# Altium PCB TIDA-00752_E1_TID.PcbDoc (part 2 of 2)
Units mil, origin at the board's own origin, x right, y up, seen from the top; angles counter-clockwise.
Board outline 600 x 3728.74 mil, 4 copper layers (Top Layer, GND, PWR, Bottom Layer), stack 62.2 mil thick; 88 components, 42 nets, 233 pads, 115 vias.
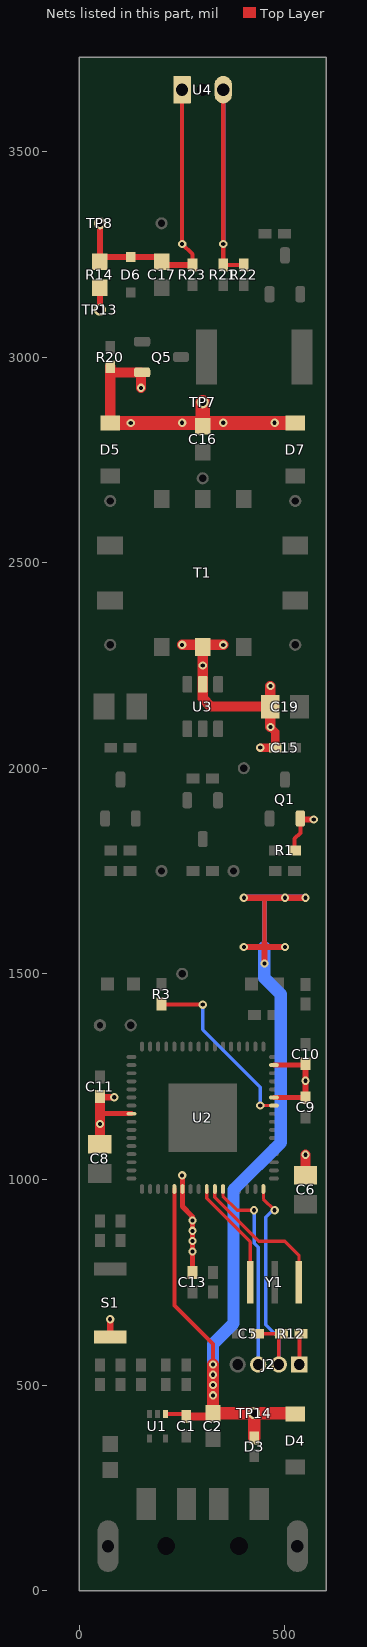
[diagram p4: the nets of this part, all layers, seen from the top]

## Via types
v1: diameter 20, hole 10, Top Layer to Bottom Layer, tented both sides, 102 vias
v2: diameter 19.68, hole 7.87, Top Layer to Bottom Layer, tented both sides, 13 vias

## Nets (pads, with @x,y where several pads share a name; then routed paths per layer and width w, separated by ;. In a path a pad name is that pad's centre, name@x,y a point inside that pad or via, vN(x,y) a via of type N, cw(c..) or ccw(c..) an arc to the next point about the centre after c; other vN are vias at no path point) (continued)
RLED: R3.1 U2.10 | length 437
  Top Layer w8: v1(440,1180) 472.76,1180 U2.10@473.23,1179.53
  Top Layer w10: R3.1@200,1426.38 201.38,1425 v1(300,1425)
  Bottom Layer w8: v1(300,1425) 300,1364.38 440,1224.38 v1(440,1180)
SBWTCK: J2.3 U2.59 | length 486.5
  Top Layer w8: U2.59@349.22,976.78 349.22,959.54 383.76,925 v1(425,925)
  Bottom Layer w8: v1(425,925) 425,845 435,835 J2.3@435,550
SBWTDIO: C5.1 J2.2 R12.2 U2.64 | length 603.1
  Top Layer w8: C5.1@433.62,625 R12.2@491.38,625 485,618.62 J2.2@485,550 ; U2.64@447.67,976.78 447.67,952.33 v1(475,925) v1@470.34,925
  Bottom Layer w8: v1(475,925) 470.34,925 453.13,907.78 453.13,646.87 485,615 J2.2@485,550
VBUS: C1.1 C2.1 C15.1 C19.1 D3.1 D4.1 Q1.2 R1.1 T1.2 TP14.1 U1.1 U2.53 U3.2 | length 4273.8
  Top Layer w10: U1.1@209.69,429.53 C1.1@254.09,429.53 ; U2.53@231.08,976.78 231.08,693.92 325,600 v1(325,550) ; 450,1565 450,1685 ; R1.1@523.62,1800 523.62,1828.62 537.4,1842.4 Q1.2@537.4,1877.76 Q1.2@540.16,1875
  Top Layer w15: v1(400,1565) 450,1565 v1(500,1565) ; v1(400,1685) 450,1685 v1(500,1685) v1(550,1685) ; v1(450,1525) 450,1575 ; Q1.2@540.16,1875 v1(570,1875)
  Top Layer w20: C1.1@260,423.62 C2.1@317.13,423.62 ; v1(440,2050) C15.1@476.38,2050 476.38,2088.18 v1(464.57,2099.99)
  Top Layer w25: v1(250,2300) T1.2@295,2300 ; T1.2@300,2295 U3.2@300,2204.13 300,2170 320.01,2149.99 C19.1@464.57,2149.99 ; T1.2@305,2300 v1(350,2300) ; v1(464.57,2099.99) C19.1@464.57,2149.99 ; v1(464.57,2200) C19.1@464.57,2149.99
  Top Layer w30: v1(325,550) C2.1@325,431.5 TP14.1@425,431.5 ; D3.1@425,371.65 TP14.1@425,431.5 ; D4.1@522.03,431.5 TP14.1@425,431.5
  GND w10: v1(400,1565) 450,1565 ; v1(400,1685) 450,1685 ; v1(450,1525) 450,1565 ; v1(500,1565) 450,1565 ; v1(550,1685) 450,1685 ; 450,1565 450,1685
  PWR w10: v1(450,1525) 450,1685
  PWR w15: v1(400,1565) v1(500,1565)
  Bottom Layer w10: 450,1565 450,1685
  Bottom Layer w15: v1(400,1565) 450,1565 v1(500,1565) ; v1(400,1685) 450,1685 v1(550,1685)
  Bottom Layer w30: v1(325,475) 325,600 375,650 375,975 490,1090 490,1450 450,1490 450,1565
  other v1: 325,500 325,525 300,2250
VCC: C16.1 D5.1 D7.1 Q5.2 R14.1 R20.2 TP7.1 TP13.1 | length 800.4
  Top Layer w15: TP13.1@50,3115 R14.1@50,3160
  Top Layer w25: D5.1@75,2839.46 R20.2@75,2976.37 ; R20.2@77.6,2962.59 150,2962.59 v1(150,2925)
  Top Layer w35: D5.1@75,2839.46 C16.1@300,2839.46 ; C16.1@300,2831.49 C16.1@300,2839.46 ; TP7.1@300,2890 C16.1@300,2839.46 ; D7.1@525,2839.46 C16.1@300,2839.46
  other v1: 125,2839.46 250,2840 350,2840 475,2840
VN: R21.1 R22.2 U4.2 | length 851.4
  Top Layer w10: U4.2@350,3650 R21.1@350,3223.62 R22.2@400,3223.62
  Bottom Layer w10: v1(350,3275) U4.2@350,3650
VP: C17.1 D6.1 R14.2 R23.2 TP8.1 U4.1 | length 1134.8
  Top Layer w10: U4.1@250,3650 v1(250,3275) 275,3250 R23.2@275,3223.62
  Top Layer w15: R14.2@50,3231.5 61.81,3243.31 D6.1@125,3243.31 188.19,3243.31 C17.1@200,3231.5 207.87,3223.62 R23.2@275,3223.62 ; R14.2@50,3240 TP8.1@50,3325
  Bottom Layer w10: v1(250,3275) U4.1@250,3650
VUSB: C6.1 C8.1 C9.1 C10.1 C11.1 C13.1 J2.1 R12.1 S1.2 U2.11 U2.15 U2.40 U2.54 | length 879.9
  Top Layer w10: J2.1@535,550 R12.1@535,621.38 ; C9.1@549.41,1199.22 C9.1@550,1198.62
  Top Layer w12: 50,1160 U2.40@126.77,1160 ; C11.1@50,1201.38 55,1196.37 C11.1@58.63,1200 ; v1(250,1010) 250.77,1009.23 U2.54@250.77,976.78 250.77,934.23 275,910 C13.1@275,773.62 ; U2.11@473.23,1199.22 C9.1@549.41,1199.22 ; U2.15@473.23,1277.96 C10.1@546.58,1277.96 ; R12.1@535,621.38 R12.1@538.62,625
  Top Layer w15: C11.1@58.63,1200 v1(85,1200) ; S1.2@75,617.32 v1(75,660) ; C9.1@550,1198.62 C10.1@550,1281.38
  Top Layer w25: C8.1@50,1085.44 v1(50,1135) C11.1@50,1201.38 ; C6.1@550,1010.43 v1(550,1060)
  other v1: 275,825 275,850 275,875 275,900 550,1240
XT2IN: U2.57 Y1.3 | length 270.7
  Top Layer w8: U2.57@309.84,976.78 309.84,954.02 415.94,847.92 Y1.3@415.94,750
XT2OUT: U2.58 Y1.1 | length 348.8
  Top Layer w8: U2.58@329.53,976.78 329.53,956.78 436.31,850 500,850 534.06,815.94 Y1.1@534.06,750
pads on no net: J1.7 J1.8 U2.1 U2.2 U2.3 U2.4 U2.5 U2.6 U2.7 U2.12 U2.13 U2.19 U2.21 U2.22 U2.23 U2.25 U2.26 U2.27 U2.29 U2.31 U2.32 U2.33 U2.34 U2.35 U2.36 U2.37 U2.38 U2.41 U2.43 U2.44 U2.45 U2.46 U2.47 U2.48 U2.60 U2.61 U2.62 U2.63 U3.6 U4.MH

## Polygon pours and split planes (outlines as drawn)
GND on Top Layer "Component Side-No Net 3" (solid, remove dead copper, pour order 42): 190,145 185,140 140,140 135,145 135,310 140,315 185,315 190,310 190,145
ISOGND on GND "Signal Layer 1-No Net" (solid, remove dead copper, pour order 9): 0,2625 600,2625 600,3350 0,3350 0,2625
GND on GND "Signal Layer 1-No Net 1" (solid, remove dead copper, pour order 11): 0,2325 0,1650 600,1650 600,2325 0,2325
GND on GND "Signal Layer 1-No Net 2" (solid, remove dead copper, pour order 34): 600,0 0,0 0,1600 600,1600 600,0
VCC on PWR "Component Side-No Net 1" (solid, remove dead copper, pour order 17): 600,2800 0,2800 0,3200 120,3200 125,3195 125,3080 130,3075 600,3075 600,2800
VUSB on PWR "Signal Layer 2-No Net" (solid, remove dead copper, pour order 32): 600,500 0,500 0,1500 600,1500 600,500
VBUS on PWR "Signal Layer 2-No Net 1" (solid, remove dead copper, pour order 36): 600,1650 0,1650 0,2325 600,2325 600,1650
GND on Bottom Layer "Solder Side-No Net" (solid, remove dead copper, pour order 52): 0,0 0,1600 600,1600 600,0 0,0
GND on Bottom Layer "Solder Side-No Net 1" (solid, remove dead copper, pour order 54): 600,1650 0,1650 0,2325 600,2325 600,1650
ISOGND on Bottom Layer "Solder Side-No Net 2" (solid, remove dead copper, pour order 56): 0,2625 0,3350 600,3350 600,2625 0,2625

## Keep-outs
Keep-Out Layer:
  lines w5: 600,0 600,0
  lines w10: -5,-5 -5,3733.74 605,3733.74 605,-5 -5,-5
  text ".Layer_Name" at 577,-1758.49 h60

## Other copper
Top Layer:
  rectangle net EN_PWR: 135,1540 165,1590
  rectangle net DATA_OUT: 235,1540 265,1590
  rectangle net DATA_OUT_NOT: 335,1540 365,1590
  rectangle net VBUS: 435,1540 465,1590
  rectangle net EN_PWR: 135,1660 165,1710
  rectangle net DATA_OUT: 235,1660 265,1710
  rectangle net DATA_OUT_NOT: 335,1660 365,1710
  rectangle net VBUS: 435,1660 465,1710
  rectangle net VP: 235,3410 265,3460
  rectangle net VN: 335,3410 365,3460
  rectangle net VP: 235,3290 265,3340
  rectangle net VN: 335,3290 365,3340
  text ".Layer_Name" at 577,-1758.49 h60
GND:
  text "GND" at 704,-1754 h40
PWR:
  text "PWR" at 694,-1760 h40
Bottom Layer:
  rectangle net GND: 135,1540 165,1590
  rectangle net GND: 235,1540 265,1590
  rectangle net GND: 335,1540 365,1590
  rectangle net VBUS: 435,1540 465,1590
  rectangle net GND: 135,1660 165,1710
  rectangle net GND: 235,1660 265,1710
  rectangle net GND: 335,1660 365,1710
  rectangle net VBUS: 435,1660 465,1710
  rectangle net VP: 235,3410 265,3460
  rectangle net VN: 335,3410 365,3460
  rectangle net VP: 235,3290 265,3340
  rectangle net VN: 335,3290 365,3340
  text ".Layer_Name" at 577,-1758.49 h60

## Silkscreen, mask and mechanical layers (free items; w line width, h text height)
Top Overlay:
  circle w6: c500,1000 r5
  circle w6: c200,2255 r5
  circle w6: c437,275 r5
  circle w6: c337,2240 r5
  circle w6: c250,3580 r5
  circle w6: c210,455 r5
  lines w6: 62.79,13 62.79,42 ; 102,147.64 496,147.64 ; 537.2,11.2 537.2,42
  lines w10: 5,5 5,2330 595,2330 595,5 5,5 ; 5,2620 595,2620 595,3724 5,3724 5,2620
  text "LMT01" at 35,3650 h50
  text ".Layer_Name" at 577,-1758.49 h60
Bottom Overlay:
  lines w10: 5,5 595,5 595,2330 5,2330 5,5 ; 5,2620 595,2620 595,3724 5,3724 5,2620
  text "Barrier" at 35,2600 h40 r180
  text "Isolation" at 575,2575 h40
  text "Isolation" at 25,2375 h40 r180
  text "Barrier" at 565,2350 h40
  text ".PCB_Rev" at 500,1225 h60 r270
  text ".PRJ_Number" at 500,625 h60 r270
  text ".Layer_Name" at 577,-1758.49 h60
Top Paste:
  text ".Layer_Name" at 577,-1758.49 h60
Bottom Paste:
  text ".Layer_Name" at 577,-1758.49 h60
Top Solder:
  region: 140,1590 135,1585 135,1545 140,1540 160,1540 165,1545 165,1585 160,1590
  region: 240,1590 235,1585 235,1545 240,1540 260,1540 265,1545 265,1585 260,1590
  region: 340,1590 335,1585 335,1545 340,1540 360,1540 365,1545 365,1585 360,1590
  region: 440,1590 435,1585 435,1545 440,1540 460,1540 465,1545 465,1585 460,1590
  region: 140,1710 135,1705 135,1665 140,1660 160,1660 165,1665 165,1705 160,1710
  region: 240,1710 235,1705 235,1665 240,1660 260,1660 265,1665 265,1705 260,1710
  region: 340,1710 335,1705 335,1665 340,1660 360,1660 365,1665 365,1705 360,1710
  region: 440,1710 435,1705 435,1665 440,1660 460,1660 465,1665 465,1705 460,1710
  region: 340,3460 335,3455 335,3415 340,3410 360,3410 365,3415 365,3455 360,3460
  region: 240,3460 235,3455 235,3415 240,3410 260,3410 265,3415 265,3455 260,3460
  region: 340,3340 335,3335 335,3295 340,3290 360,3290 365,3295 365,3335 360,3340
  region: 240,3340 235,3335 235,3295 240,3290 260,3290 265,3295 265,3335 260,3340
  text ".Layer_Name" at 577,-1758.49 h60
  text ".Layer_Name" at 577,-1758.49 h60
Bottom Solder:
  region: 140,1590 135,1585 135,1545 140,1540 160,1540 165,1545 165,1585 160,1590
  region: 240,1590 235,1585 235,1545 240,1540 260,1540 265,1545 265,1585 260,1590
  region: 340,1590 335,1585 335,1545 340,1540 360,1540 365,1545 365,1585 360,1590
  region: 440,1590 435,1585 435,1545 440,1540 460,1540 465,1545 465,1585 460,1590
  region: 140,1710 135,1705 135,1665 140,1660 160,1660 165,1665 165,1705 160,1710
  region: 240,1710 235,1705 235,1665 240,1660 260,1660 265,1665 265,1705 260,1710
  region: 340,1710 335,1705 335,1665 340,1660 360,1660 365,1665 365,1705 360,1710
  region: 440,1710 435,1705 435,1665 440,1660 460,1660 465,1665 465,1705 460,1710
  region: 240,3460 235,3455 235,3415 240,3410 260,3410 265,3415 265,3455 260,3460
  region: 340,3460 335,3455 335,3415 340,3410 360,3410 365,3415 365,3455 360,3460
  region: 240,3340 235,3335 235,3295 240,3290 260,3290 265,3295 265,3335 260,3340
  region: 340,3340 335,3335 335,3295 340,3290 360,3290 365,3295 365,3335 360,3340
  text ".Layer_Name" at 577,-1758.49 h60
Drill Guide:
  text ".Layer_Name" at 577,-1758.49 h60
Mechanical 1:
  lines w5: 0,1600 cw(c0,1625) 0,1650 110,1650 cw(c110,1625) 110,1600 0,1600 ; 0,3350 cw(c0,3375) 0,3400 210,3400 cw(c210,3375) 210,3350 0,3350 ; 190,1600 cw(c190,1625) 190,1650 210,1650 cw(c210,1625) 210,1600 190,1600 ; 290,1600 cw(c290,1625) 290,1650 310,1650 cw(c310,1625) 310,1600 290,1600 ; 290,3350 cw(c290,3375) 290,3400 310,3400 cw(c310,3375) 310,3350 290,3350 ; 390,1600 cw(c390,1625) 390,1650 410,1650 cw(c410,1625) 410,1600 390,1600 ; 390,3350 cw(c390,3375) 390,3400 600,3400 cw(c600,3375) 600,3350 390,3350 ; 490,1600 cw(c490,1625) 490,1650 600,1650 cw(c600,1625) 600,1600 490,1600
  lines w10: 0,0 0,3728.74 600,3728.74 600,0 0,0
Mechanical 2:
  rectangle: 0,-1175 125,-1050
  rectangle: 125,-1300 500,-1175
  lines w7: 0,-1175 1000,-1175 ; 125,-1300 125,-1050 ; 250,-1300 250,-1050 ; 500,-1300 500,-1050 ; 750,-1300 750,-1050 ; 0,-1300 1000,-1300 1000,-1050 0,-1050 0,-1300
Mechanical 3:
  text ".Layer_Name" at 577,-1758.49 h60
Mechanical 4:
  text ".Layer_Name" at 577,-1758.49 h60
Mechanical 5:
  circle w6: c250,3645 r5
  circle w6: c462,3137 r6.4
  circle w6: c136,3038 r7.62
  circle w6: c62,1862 r5.39
  circle w6: c336,1934 r4.47
  circle w6: c462,1867 r5.39
  circle w6: c494,1001 r4.47
  circle w6: c209,444 r3.16
  circle w6: c536,551 r9.49
  circle w6: c436,253 r6.26
  lines w10: -292,-1830.17 6308,-1830.17 ; -292,-1626.83 6310,-1626.83 ; -292,-1423.5 -292,-2033.5 3713,-2033.5 6310,-2033.5 6310,-1423.5 -291.5,-1423.5 -291.5,-2033.5 1284,-2033.5 ; 2173,-2033.5 2173,-1423.5 ; 3440,-1626.83 3440,-1423.5 ; 4280,-1626.83 4280,-1423.5 ; 4902,-2040 4902,-1837.17
  text "COMPONENTS MARKED 'DNP' SHOULD NOT BE POPULATED." at 1153.5,-1218.5 h25
  text "ASSEMBLY VARIANT:" at 1153,-1334 h25
  text ".VariantName" at 2189,-1334 h25
  text "PCB VIEWED FROM TOP SIDE" at -228.5,-1555.67 h25
  text "BOARD #:" at 2248,-1555.67 h25
  text ".PRJ_Number" at 2793.5,-1555.67 h25
  text "REV:" at 3638,-1555.67 h25
  text ".PCB_Rev" at 3929.5,-1555.67 h25
  text "SVN REV:" at 4476,-1555.67 h25
  text ".VersionControl_RevNumber" at 4982,-1555.67 h25
  text "LAYER NAME = Assembly Top" at -70,-1749 h30
  text "TID #:" at 2248,-1759 h25
  text ".TID" at 2793.5,-1759 h25
  text "PLOT NAME =" at -228.5,-1964.34 h25
  text ".plot_File_Name" at 577,-1964.34 h25
  text "GENERATED    :" at 2250,-1964.34 h25
  text ".Print_Date" at 3119.5,-1964.34 h25
  text ".Print_Time" at 3848.5,-1964.34 h25
  text "TEXAS INSTRUMENTS" at 5113,-1964.34 h25
Mechanical 6:
  lines w10: -292.5,-1627.33 6309.5,-1627.33 ; -290.5,-1830.67 6309.5,-1830.67 ; 1115.5,-2040.5 1115.5,-1837.67 ; 1737.5,-1627.33 1737.5,-1424 ; 2577.5,-1627.33 2577.5,-1424 ; 3844.5,-2034 3844.5,-1424 ; 4733.5,-2034 6309,-2034 6309,-1424 -292.5,-1424 -292.5,-2034 2304.5,-2034 6309.5,-2034 6309.5,-1424
  text "COMPONENTS MARKED 'DNP' SHOULD NOT BE POPULATED." at 6102,-1218 h60
  text ".VariantName" at 5058,-1334 h60
  text "ASSEMBLY VARIANT:" at 6097,-1334 h60
  text ".VersionControl_RevNumber" at 1035.5,-1556.17 h60
  text "SVN REV:" at 1541.5,-1556.17 h60
  text ".PCB_Rev" at 2088,-1556.17 h60
  text "REV:" at 2379.5,-1556.17 h60
  text ".PRJ_Number" at 3224,-1556.17 h60
  text "BOARD #:" at 3769.5,-1556.17 h60
  text "PCB VIEWED FROM BOTTOM SIDE" at 6246,-1556.17 h60
  text ".TID" at 3224,-1759.5 h60
  text "TID #:" at 3769.5,-1759.5 h60
  text "TEXAS INSTRUMENTS" at 904.5,-1964.84 h60
  text ".Print_Time" at 2169,-1964.84 h60
  text ".Print_Date" at 2898,-1964.84 h60
  text "GENERATED    :" at 3767.5,-1964.84 h60
  text ".plot_File_Name" at 5440.5,-1964.84 h60
  text "PLOT NAME =" at 6246,-1964.84 h60
Mechanical 9:
  drawing of 59 lines, arcs and shapes, not listed
  text "1" at 739.84,7136.5 h70
  text "2" at 3235.5,7136.5 h70
  text "3" at 5724.84,7136.5 h70
  text "4" at 8231.51,7136.5 h70
  text "5" at 10730.5,7136.5 h70
  text "6" at 13235.5,7136.5 h70
  text "A" at -416.5,5993.5 h70
  text "A" at 14383.5,5993.5 h70
  text "B" at -416.5,3613.5 h70
  text "B" at 14383.5,3613.5 h70
  text "C" at -416.5,1238.5 h70
  text "C" at 14383.5,1238.5 h70
  text "PROJECT TITLE:" at 11343.5,-622.5 h45
  text ".PRJ_Title" at 11393.5,-755.83 h70
  text "DESIGNED FOR:" at 11343.5,-923.5 h45
  text ".PRJ_Customer" at 11393.5,-1063.5 h70
  text "D" at -416.5,-1131.5 h70
  text "D" at 14383.5,-1131.5 h70
  text "FILE NAME:" at 11343.5,-1223.5 h45
  text ".PCB_File_Name_No_Path" at 11393.5,-1343.5 h70
  text "Texas Instruments (TI) and/or its licensors do not warrant the accuracy or completeness of this specification" at 6374,-1505.34 h45
  text "ENGINEER:" at 11343.5,-1513.5 h45
  text "LAYOUT BY:" at 12848.5,-1513.5 h45
  text "or any information contained therein. TI and/or its licensors do not warrant that this design will meet" at 6329.01,-1618 h45
  text ".PRJ_Engineer" at 11393.5,-1668.49 h70
  text ".PCB_Layout" at 12899,-1668.49 h70
  text "the specifications, will be suitable for your application or fit for any particular purpose, or will operate in" at 6329.01,-1730.67 h45
  text "ALTIUM DESIGNER VERSION:" at 12848.5,-1823.5 h45
  text "an implementation. TI and/or its licensors do not warrant that the design is production worthy. You should" at 6329.01,-1843.33 h45
  text "completely validate and test your design implementation to confirm the system functionality for your application." at 6374,-1956 h45
  text ".print_Scale" at 11393.5,-1956.83 h70
  text ".Application_BuildNumber" at 12899,-1956.83 h70
  text "1" at 739.84,-2163.5 h70
  text "2" at 3235.5,-2163.5 h70
  text "3" at 5724.84,-2163.5 h70
  text "4" at 8231.51,-2163.5 h70
  text "5" at 10730.5,-2163.5 h70
  text "6" at 13235.5,-2163.5 h70
Mechanical 10:
  drawing of 228 lines, arcs and shapes, not listed
  text "DESIGN INFORMATION" at 12382.02,5910 h60
  text "(REFER ALSO ARRAY/PANEL PROFILING INFORMATION)" at 12020.46,5748.29 h60
  text "BOARD SIZE" at 11334.46,5744 h60
  text "600MIL" at 11796.78,5616.18 h60
  text "X" at 12302.46,5616.18 h60
  text "3728.74MIL" at 12533.78,5616.18 h60
  text "Number of Layers :" at 11737.46,5419 h60
  text "4" at 12832.27,5409 h60
  text "MIN. TRACK WIDTH:" at 11737.46,5280 h60
  text "8" at 12833.7,5280 h60
  text "MIL" at 12988.46,5280 h60
  text "7.874" at 12700,5150 h60
  text "MIN. CLEARANCE:" at 11737.46,5148 h60
  text "MIL" at 12988.46,5148 h60
  text "MIN. VIA DRILL SIZE:" at 11737.46,5016 h60
  text "MIL" at 12988.46,5016 h60
  text "7.874" at 12701,5010 h60
  text "3.785 MIL" at 12432.46,4874.29 h60
  text "MINIMUM ANNULAR RING" at 11408.23,4870 h60
  text "EXTERNAL" at 13140.46,4870 h60
  text "PER" at 11608.23,4752 h60
  text "IPC-D-275 CLASS 2 LEVEL C" at 11828.23,4752 h60
  text "MIL, HOLES" at 13316.46,4639.71 h60
  text "+/-" at 12924,4639 h60
  text "+/-" at 13778,4639 h60
  text "REGISTRATION TOLERANCES:" at 11408.23,4634 h60
  text "METAL" at 12608,4634 h60
  text "5" at 13184.2,4634 h60
  text "3" at 14017.2,4634 h60
  text "MIL" at 14133.46,4634 h60
  text "MATERIAL:" at 11333.46,4424.54 h60
  text "FR-4 High Tg" at 12319.9,4284.21 h60
  text "FR-408" at 11754.46,4275.64 h60
  text "OTHER" at 13242.46,4275.64 h60
  text "X" at 12165,4275 h60
  text "63 MIL (1.6mm) +/-10%" at 12074.56,4112.92 h60
  text "THICKNESS:" at 11408.23,4108.64 h60
  text "X" at 11946.4,4108.64 h60
  text "OTHER" at 13359.46,4108.64 h60
  text "TOLERANCE:" at 11408.23,3950.64 h60
  text "X" at 12247.53,3950.64 h60
  text "ANSI IPC-6012 TYPE 3 CLASS 2" at 12434.48,3950.64 h60
  text "OTHER +/-" at 12434.46,3794.64 h60
  text "BOW & TWIST:" at 11408.23,3637.64 h60
  text "X" at 12247.53,3637.64 h60
  text "ANSI IPC-6012 TYPE 3 CLASS 2" at 12434.48,3637.64 h60
  text "OTHER +/-" at 12434.46,3479.13 h60
  text "COPPER THICKNESS (FINISHED):" at 11333.46,3343.64 h60
  text "1.4MIL (1oz)" at 12213.46,3190.92 h60
  text "2MIL (1.4oz)" at 12980.46,3190.92 h60
  text "2.8MIL (2oz)" at 13707.46,3190.92 h60
  text "OUTER:" at 11690.46,3186.64 h60
  text "X" at 12085,3186 h60
  text "1.4MIL (1oz)" at 12213.46,3033.92 h60
  text "2.8MIL (2oz)" at 12980.46,3033.92 h60
  text "N/A" at 13707,3034.29 h60
  text "INNER SIGNAL:" at 11401.38,3029.64 h60
  text "X" at 12080,3027 h60
  text "DRILLING:" at 11333.46,2890.64 h60
  text "REFERENCE:" at 11408.23,2773.64 h60
  text "X" at 12056.46,2773.64 h60
  text "AS SHOWN" at 12243.46,2773.64 h60
  text "X" at 12957.46,2773.64 h60
  text "NC_DRILL FILES" at 13094.46,2773.64 h60
  text "PTH MIN COPPER THICKNESS:" at 11408.23,2615.64 h60
  text "X" at 12758.46,2615.64 h60
  text "1MIL" at 12895.46,2615.64 h60
  text "OTHER" at 13392.46,2615.64 h60
  text "BOARD FINISH:" at 11333.46,2456.64 h60
  text "SILKSCREEN:" at 11488.68,2338.64 h60
  text "X" at 12437.46,2338.64 h60
  text "TOP" at 12563.46,2338.64 h60
  text "X" at 12947.46,2338.64 h60
  text "BOTTOM" at 13074.46,2338.64 h60
  text "SILKSCREEN COLOR:" at 11488.68,2171.64 h60
  text "X" at 12436.42,2171.64 h60
  text "WHITE" at 12563.46,2171.64 h60
  text "OTHER" at 13074.46,2171.64 h60
  text "SOLDER RESIST COLOR:" at 11488.68,2001.64 h60
  text "X" at 12056.42,1842.44 h60
  text "GREEN" at 12183.46,1842.44 h60
  text "BLUE" at 12774.46,1842.44 h60
  text "OTHER" at 13312.46,1842.44 h60
  text "IMMERSION GOLD (ENIG)" at 12394.46,1653.92 h60
  text "ENEPIG" at 13732,1650.64 h60
  text "SURFACE FINISH:" at 11333.46,1649.64 h60
  text "X" at 12207.51,1649.64 h60
  text "IMM. TIN/SILVER OR EQUIV" at 11663,1492.64 h60
  text "OTHER" at 13094.46,1492.64 h60
  text "ARRAY/PANEL:" at 11333.46,1313.64 h60
  text "CUT AND TRIM PER MECH LAYER 1" at 12394.46,1309.35 h60
  text "N.C. ROUTE" at 12394.46,1157.64 h60
  text "X" at 13073.46,1157.64 h60
  text "V. SCORE" at 13260.46,1157.64 h60
  text "CERTIFICATION:" at 11333.46,1020.64 h60
  text "MATERIALS AND WORKMANSHIP FOR ALL PCBS" at 12058.46,1020.64 h60
  text "TO MEET OR EXCEED THE REQUIREMENTS OF:" at 12058.46,922.64 h60
  text "X" at 11684.96,786.13 h60
  text "ANSI IPC-A-600F CLASS ->" at 11823.96,786.13 h60
  text "X" at 13463.02,786.13 h60
  text "2" at 13581.96,786.14 h60
  text "1" at 13266.96,784.64 h60
  text "3" at 13935.96,784.64 h60
  text "X" at 11687.02,626.64 h60
  text "UL 94V-0" at 11823.96,626.64 h60
  text "X" at 12499.02,626.64 h60
  text "RoHS" at 12635.96,626.64 h60
  text "OTHER" at 13280.36,626.64 h60
  text "PER ORDER" at 13677.42,626.64 h60
  text "X" at 13314,497 h60
  text "VIA TENTING:" at 12551,493 h60
  text "ADDITIONAL REQUIREMENTS:" at 11333.46,485.64 h60
  text "YES" at 13100.67,483.92 h60
  text "NO" at 13465.47,478.69 h60
  text "MICROSECTION:" at 11408.23,370.64 h60
  text "YES" at 12313.96,370.64 h60
  text "IMPEDANCE CONTROL:" at 12573,364 h60
  text "YES" at 13557,363 h60
  text "X" at 14099,356 h60
  text "NO" at 13932.47,345.69 h60
  text "REQUIRED" at 13175.46,214.49 h60
  text "BARE BOARD ELEC. TEST:" at 11408.23,211.64 h60
  text "NONE" at 12713.96,211.64 h60
  text "X" at 13048.46,211.64 h60
  text "PER ORDER" at 13767.46,211.64 h60
  text "MANUFACTURER'S UL:" at 11408.23,54.64 h60
  text "RAIL" at 12573.96,50.35 h60
  text "METAL" at 13065.77,50.35 h60
  text "X" at 13441,50 h60
  text "SILK" at 13577.46,50.35 h60
Mechanical 11:
  lines w10: -292,-1830.17 6308,-1830.17 ; -292,-1626.83 6310,-1626.83 ; -292,-1423.5 -292,-2033.5 3713,-2033.5 6310,-2033.5 6310,-1423.5 -291.5,-1423.5 -291.5,-2033.5 1284,-2033.5 ; 2173,-2033.5 2173,-1423.5 ; 3440,-1626.83 3440,-1423.5 ; 4280,-1626.83 4280,-1423.5 ; 4902,-2040 4902,-1837.17
  text "ALL ARTWORK VIEWED FROM TOP SIDE" at -228.5,-1555.67 h60
  text "BOARD #:" at 2248,-1555.67 h60
  text ".PRJ_Number" at 2793.5,-1555.67 h60
  text "REV:" at 3638,-1555.67 h60
  text ".PCB_Rev" at 3929.5,-1555.67 h60
  text "SVN REV:" at 4476,-1555.67 h60
  text ".VersionControl_RevNumber" at 4982,-1555.67 h60
  text "LAYER NAME =" at -228.5,-1758.49 h60
  text "TID #:" at 2248,-1759 h60
  text ".TID" at 2793.5,-1759 h60
  text "PLOT NAME =" at -228.5,-1964.34 h60
  text ".plot_File_Name" at 577,-1964.34 h60
  text "GENERATED    :" at 2250,-1964.34 h60
  text ".Print_Date" at 3119.5,-1964.34 h60
  text ".Print_Time" at 3848.5,-1964.34 h60
  text "TEXAS INSTRUMENTS" at 5113,-1964.34 h60
Mechanical 12:
  lines w6: 11361,6560 13911,6560 ; 11361,6664.4 13911,6664.4 ; 11301,6075 ccw(c11335,6075) 11335,6041 13937,6041 ccw(c13937,6075) 13971,6075 13971,6781 ccw(c13937,6781) 13937,6815 11335,6815 ccw(c11335,6781) 11301,6781 11301,6075
  text "Layer Stack Up Detail for: TIDA-00752_E1" at 11361,6697.1 h57
  text "Layer" at 11361,6625.4 h24
  text "Gerber" at 12256.81,6625.4 h24
  text "Copper" at 12820.33,6625.4 h24
  text "Dielectric" at 13423.04,6625.4 h24
  text "Name" at 11361,6577.4 h24
  text "Document" at 12256.81,6577.4 h24
  text "Thickness" at 12820.33,6577.4 h24
  text "Material" at 13423.04,6577.4 h24
  text "Top Solder Mask" at 11361,6484.44 h34
  text "(.GTS)" at 12256.81,6484.44 h34
  text "Solder Resist" at 13423.04,6484.44 h34
  text "Top Layer" at 11361,6387.69 h34
  text "(.GTL)" at 12256.81,6387.69 h34
  text "1.4mil" at 12820.33,6387.69 h34
  text "FR-4 High Tg" at 13452,6387 h34
  text "FR-4 High Tg" at 13451,6322 h34
  text "(.G1)" at 12260.81,6320.69 h34
  text "1.4mil" at 12821.33,6316.69 h34
  text "GND" at 11365,6314 h34
  text "FR-4 High Tg" at 13452,6257 h34
  text "1.4mil" at 12824.33,6250.69 h34
  text "(.G2)" at 12260.81,6247.69 h34
  text "PWR" at 11366,6238 h34
  text "FR-4 High Tg" at 13454,6168 h34
  text "Bottom Layer" at 11367,6158 h34
  text "(.GBL)" at 12265,6157 h34
  text "1.4mil" at 12825,6151 h34
  text "Solder Resist" at 13417,6084 h34
  text "(.GBS)" at 12262,6077 h34
  text "Bottom Solder Mask" at 11364,6072 h34
Mechanical 13:
  text ".Layer_Name" at 577,-1758.49 h60
Mechanical 14:
  text ".Layer_Name" at 577,-1758.49 h60
Mechanical 15:
  text ".Layer_Name" at 577,-1758.49 h60
Mechanical 16:
  text ".Layer_Name" at 577,-1758.49 h60
Drill Drawing:
  circle w1: c2482.72,3557.4 r24.89
  circle w1: c2482.72,2661.48 r14.93
  circle w1: c2482.72,2661.48 r24.89
  lines w1: 2457.83,2785.92 2482.72,2798.36 2507.6,2785.92 2495.16,2810.8 2507.6,2835.69 2482.72,2823.25 2457.83,2835.69 2470.27,2810.8 2457.83,2785.92 ; 2457.83,2985.01 2507.6,2985.01 2482.72,2935.24 2457.83,2985.01 ; 2457.83,3097 2470.27,3097 2470.27,3084.56 2495.16,3084.56 2495.16,3097 2507.6,3097 2507.6,3121.89 2495.16,3121.89 2495.16,3134.33 2470.27,3134.33 2470.27,3121.89 2457.83,3121.89 2457.83,3097 ; 2457.83,3258.76 2482.72,3233.88 2507.6,3258.76 2482.72,3283.65 2457.83,3258.76 ; 2457.83,3383.2 2507.6,3383.2 2507.6,3432.97 2457.83,3432.97 2457.83,3383.2 ; 2457.83,3681.84 2457.83,3694.28 2470.27,3706.72 2457.83,3719.17 2457.83,3731.61 2470.27,3731.61 2482.72,3719.17 2495.16,3731.61 2507.6,3731.61 2507.6,3719.17 2495.16,3706.72 2507.6,3694.28 2507.6,3681.84 2495.16,3681.84 2482.72,3694.28 2470.27,3681.84 2457.83,3681.84 ; 2457.83,3843.6 2470.27,3843.6 2482.72,3831.16 2495.16,3843.6 2507.6,3843.6 2495.16,3856.04 2507.6,3868.49 2495.16,3868.49 2482.72,3880.93 2470.27,3868.49 2457.83,3868.49 2470.27,3856.04 2457.83,3843.6
  lines w12: 2390,2591.8 4508.02,2591.8 ; 2390,3935.68 4508.02,3935.68 ; 2760.36,2442.48 2760.36,4085 ; 3117.36,2442.48 3117.36,4085 ; 3778.93,2442.48 3778.93,4085 ; 4063.07,2442.48 4063.07,4085 ; 2390,2442.48 4508.02,2442.48 4508.02,4085 2390,4085 2390,2442.48
  text "Symbol" at 2479.59,3980.48 h72
  text "Quantity" at 2805.16,3980.48 h72
  text "Finished Hole Size" at 3162.16,3980.48 h72
  text "Plated" at 3823.72,3980.48 h72
  text "Hole Type" at 4107.86,3980.48 h72
  text "1" at 2805.16,3831.16 h60
  text "29.53mil (0.750mm)" at 3162.16,3831.16 h60
  text "NPTH" at 3823.72,3831.16 h60
  text "Round" at 4107.86,3831.16 h60
  text "2" at 2805.16,3681.84 h60
  text "43.31mil (1.100mm)" at 3162.16,3681.84 h60
  text "NPTH" at 3823.72,3681.84 h60
  text "Round" at 4107.86,3681.84 h60
  text "13" at 2805.16,3532.52 h60
  text "7.87mil (0.200mm)" at 3162.16,3532.52 h60
  text "PTH" at 3823.72,3532.52 h60
  text "Round" at 4107.86,3532.52 h60
  text "102" at 2805.16,3383.2 h60
  text "10.00mil (0.254mm)" at 3162.16,3383.2 h60
  text "PTH" at 3823.72,3383.2 h60
  text "Round" at 4107.86,3383.2 h60
  text "1" at 2805.16,3233.88 h60
  text "15.00mil (0.381mm)" at 3162.16,3233.88 h60
  text "PTH" at 3823.72,3233.88 h60
  text "Round" at 4107.86,3233.88 h60
  text "15" at 2805.16,3084.56 h60
  text "17.72mil (0.450mm)" at 3162.16,3084.56 h60
  text "PTH" at 3823.72,3084.56 h60
  text "Round" at 4107.86,3084.56 h60
  text "4" at 2805.16,2935.24 h60
  text "25.59mil (0.650mm)" at 3162.16,2935.24 h60
  text "PTH" at 3823.72,2935.24 h60
  text "Round" at 4107.86,2935.24 h60
  text "2" at 2805.16,2785.92 h60
  text "29.53mil (0.750mm)" at 3162.16,2785.92 h60
  text "PTH" at 3823.72,2785.92 h60
  text "Round" at 4107.86,2785.92 h60
  text "2" at 2805.16,2636.6 h60
  text "30.00mil (0.762mm)" at 3162.16,2636.6 h60
  text "PTH" at 3823.72,2636.6 h60
  text "Slot" at 4107.86,2636.6 h60
  text "142 Total" at 2805.16,2487.28 h60
  text ".Layer_Name" at 577,-1758.49 h60

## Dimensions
0,-1300 to 1000,-1300 on Mechanical 2
0,3728.74 to 0,0 on Mechanical 2
600,3728.74 to 0,3728.74 on Mechanical 2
